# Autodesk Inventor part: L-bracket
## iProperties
Author: Administrator
Created: 2000-12
Part Number: L-bracket
Document SubType Name: Modeling
Designer: Administrator
Control State: 0
Master: False
Checked Out: False
PropertySet Name: Design Tracking Control
Shininess: 0.0
PropertySet Name: _Private Model Information
Density: 0.0
Volumn: 0.0
Area: 0.0
PropertySet Name: Model Information
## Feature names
1. Extrusion1
2. Hole1
